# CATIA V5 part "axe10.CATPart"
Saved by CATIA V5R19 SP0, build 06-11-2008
Part number: axe10
Publications: "taille_axe"
Bounding box of the stored display mesh (mm): x -5 to 10, y -9 to 9, z -9 to 9
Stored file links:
  H:\EU_thinkMotion\IAO_2010\iao\IAO_MMS_Groupe3\PB\jpeguet\jpeguet_IAO\jpeguet_IAO\axe10.CATPart
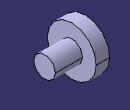
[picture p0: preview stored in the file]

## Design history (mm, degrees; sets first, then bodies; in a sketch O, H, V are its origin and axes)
Parameters
  taille_axe = 10 mm
Body1 (main body)
  Sketch1 on yz-plane, origin (0, 0, 0), H (0, 1, 0), V (0, 0, 1)
    circle A1 centre (0, 0) radius 4
    radius A1 = 4
  Pad1: profile Sketch1, direction (1, 0, 0), length 10 {= taille_axe}
  Sketch2 on start face of Pad1, origin (0, 0, 0), H (0, -1, 0), V (0, 0, 1)
    circle A1 centre (0, 0) radius 9
  Pad2: profile Sketch2, direction (-1, 0, 0), length 5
